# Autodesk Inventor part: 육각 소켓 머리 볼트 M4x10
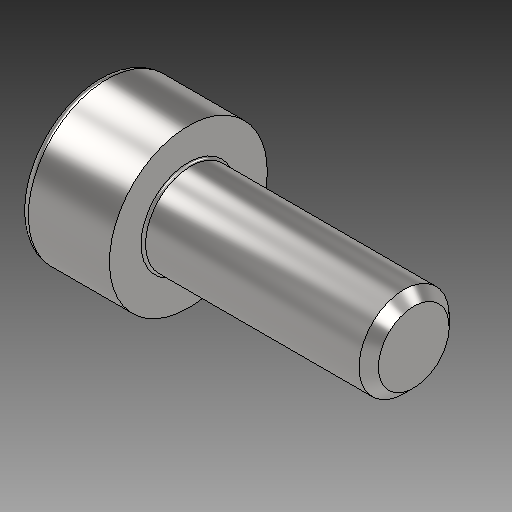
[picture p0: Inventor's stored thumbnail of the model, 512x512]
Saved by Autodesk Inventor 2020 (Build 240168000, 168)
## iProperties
Created: 2024-08
Part Number: 육각 소켓 머리 볼트 M4x10
Material: 강철, 연강
Description: 6각머리 태핑 나사
Document SubType Name: Modeling
Designer: 1강의실14
Density: 7.85 g/cm^3
Appearance: 기본값
Sending System: Autodesk Inventor 2025
Preprocessor: ST-DEVELOPER v20
Author: jhkim
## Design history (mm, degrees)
feature "Solid1"
node "솔리드1"
